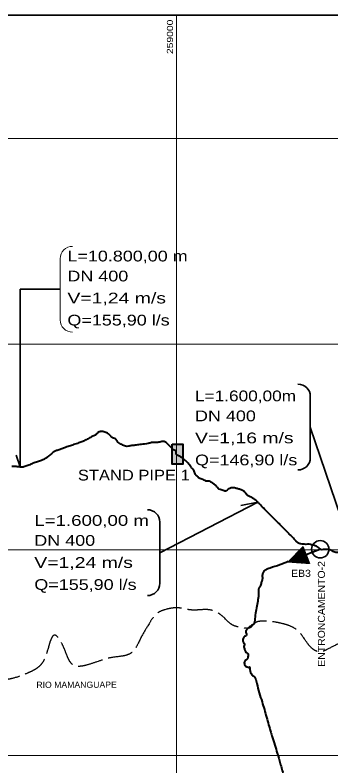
# Model space of a CAD drawing. Extents: x -4 to 42046, y -3 to 29697.
# Drawn here: x 35401 to 37843, y 13120 to 18930 of the extents above; entities that cross this region are included whole.
import ezdxf
from ezdxf.enums import TextEntityAlignment as Align

# ---------------------------------------------------------------- set-up
doc = ezdxf.new("R2010")
doc.units = 0
doc.header["$LTSCALE"] = 32
doc.linetypes.add('LONG_DASHED', pattern=[7.5, 6, -1.5])
for name, color, linetype, lineweight in [('4', 7, 'Continuous', 13), ('5', 7, 'LONG_DASHED', 25), ('6', 7, 'Continuous', 40), ('63', 7, 'Continuous', 25), ('8', 7, 'Continuous', 35)]:
    doc.layers.add(name, color=color, linetype=linetype, lineweight=lineweight)

msp = doc.modelspace()

# ---------------------------------------------------------------- hatches: boundary and pattern name
at = {"layer": '8'}
msp.add_hatch(color=256, dxfattribs=at).paths.add_polyline_path([(36615.72, 15610.25), (36697.35, 15610.25), (36697.35, 15455.76), (36615.72, 15455.76)])

# ---------------------------------------------------------------- linework, layer by layer
at = {"layer": '4'}
for p, q in [((37603.95, 14792.87), (37627.86, 14816.79)), ((37606.78, 14792.87), (37628.67, 14814.77)), ((37510.7, 14697.44), (37606.13, 14792.87)), ((37513.34, 14697.25), (37608.96, 14792.87)), ((37515.98, 14697.06), (37611.79, 14792.87)), ((37518.62, 14696.87), (37614.62, 14792.87)), ((37521.26, 14696.68), (37617.45, 14792.87)), ((37523.89, 14696.49), (37620.28, 14792.87)), ((37526.53, 14696.3), (37623.11, 14792.87)), ((37529.17, 14696.11), (37625.93, 14792.87)), ((37531.81, 14695.93), (37628.76, 14792.87)), ((37534.45, 14695.74), (37631.59, 14792.87)), ((37537.09, 14695.55), (37634.42, 14792.87)), ((37539.73, 14695.36), (37637.25, 14792.87)), ((37542.37, 14695.17), (37638.19, 14790.98)), ((37545.01, 14694.98), (37638.99, 14788.96)), ((37547.65, 14694.79), (37639.8, 14786.94)), ((37550.29, 14694.6), (37640.61, 14784.92)), ((37552.93, 14694.41), (37641.42, 14782.9)), ((37555.57, 14694.22), (37642.23, 14780.88)), ((37558.21, 14694.03), (37643.03, 14778.86)), ((37560.84, 14693.84), (37643.84, 14776.84)), ((37563.48, 14693.66), (37644.65, 14774.82)), ((37566.12, 14693.47), (37645.46, 14772.8)), ((37568.76, 14693.28), (37646.27, 14770.78)), ((37571.4, 14693.09), (37647.08, 14768.76)), ((37574.04, 14692.9), (37647.88, 14766.74)), ((37576.68, 14692.71), (37648.69, 14764.72)), ((37579.32, 14692.52), (37649.5, 14762.7)), ((37581.96, 14692.33), (37650.31, 14760.68)), ((37584.6, 14692.14), (37651.12, 14758.66)), ((37587.24, 14691.95), (37651.92, 14756.64)), ((37609.61, 14792.87), (37629.48, 14812.75)), ((37612.43, 14792.87), (37630.29, 14810.73)), ((37615.26, 14792.87), (37631.1, 14808.71)), ((37618.09, 14792.87), (37631.9, 14806.69)), ((37620.92, 14792.87), (37632.71, 14804.67)), ((37623.75, 14792.87), (37633.52, 14802.65)), ((37626.58, 14792.87), (37634.33, 14800.63)), ((37629.4, 14792.87), (37635.14, 14798.61)), ((37632.23, 14792.87), (37635.94, 14796.59)), ((37635.06, 14792.87), (37636.75, 14794.57)), ((37589.88, 14691.76), (37652.73, 14754.62)), ((37592.52, 14691.57), (37653.54, 14752.6)), ((37595.16, 14691.39), (37654.35, 14750.58)), ((37597.79, 14691.2), (37655.16, 14748.56)), ((37600.43, 14691.01), (37655.97, 14746.54)), ((37603.07, 14690.82), (37656.77, 14744.52)), ((37605.71, 14690.63), (37657.58, 14742.5)), ((37608.35, 14690.44), (37658.39, 14740.48)), ((37610.99, 14690.25), (37659.2, 14738.46)), ((37613.63, 14690.06), (37660.01, 14736.44)), ((37616.27, 14689.87), (37660.81, 14734.42)), ((37618.91, 14689.68), (37661.62, 14732.4)), ((37621.55, 14689.49), (37662.43, 14730.38)), ((37624.19, 14689.31), (37663.24, 14728.36)), ((37626.83, 14689.12), (37664.05, 14726.34)), ((37629.47, 14688.93), (37664.85, 14724.32)), ((37632.11, 14688.74), (37665.66, 14722.3)), ((37634.74, 14688.55), (37666.47, 14720.28)), ((37637.38, 14688.36), (37667.28, 14718.26)), ((37640.02, 14688.17), (37668.09, 14716.23)), ((37642.66, 14687.98), (37668.9, 14714.21)), ((37645.3, 14687.79), (37669.7, 14712.19)), ((37647.94, 14687.6), (37670.51, 14710.17)), ((37650.58, 14687.41), (37671.32, 14708.15)), ((37653.22, 14687.22), (37672.13, 14706.13)), ((37655.86, 14687.04), (37672.94, 14704.11)), ((37658.5, 14686.85), (37673.74, 14702.09)), ((37661.14, 14686.66), (37674.55, 14700.07)), ((37663.78, 14686.47), (37675.36, 14698.05)), ((37666.42, 14686.28), (37676.17, 14696.03)), ((37669.05, 14686.09), (37676.98, 14694.01)), ((37671.69, 14685.9), (37677.79, 14691.99)), ((37674.33, 14685.71), (37678.59, 14689.97)), ((37676.97, 14685.52), (37679.4, 14687.95)), ((37679.61, 14685.33), (37680.21, 14685.93))]:
    msp.add_line(p, q, dxfattribs=at)
msp.add_lwpolyline([(37680.47, 14685.27), (37509.34, 14697.54), (37627.58, 14817.5)], close=True, dxfattribs=at)
at = {"layer": '4', "lineweight": 35}
msp.add_ellipse((37760.11, 14797), major_axis=(67.17, 0), ratio=0.998913, dxfattribs=at)
at = {"layer": '5'}
for points in [[(36427.45, 14204.37), (36372.08, 14108.75), (36305.48, 13999.35), (36136.53, 13956.58), (35847.84, 13902.88), (35759.27, 14075.23), (35713.31, 14131.45), (35636.31, 13965.66), (35506.34, 13841.99), (35249.2, 13841.22), (35248.87, 13953.94), (35237.98, 13953.91), (35181.75, 14017.15), (35181.99, 13936.13), (35083.37, 13935.84), (34941.94, 14111.55), (34878.67, 14069.09), (34924.95, 13903.67), (34925.39, 13755.72), (34784.49, 13755.3), (34615.25, 13811.16), (34245.39, 13810.06), (34122.35, 13832.82), (34069.68, 13894.69), (33994.34, 13957.69), (33936.87, 14030.29), (33885.43, 14077.85), (33815, 14095.54), (33725.5, 14107.2), (33699.12, 14152.45), (33675.07, 14216.8), (33661.79, 14268.06), (33661.7, 14300.26), (33613.98, 14300.12), (33567.46, 14299.98), (33502.97, 14324.84), (33452.79, 14349.75), (33398.87, 14331.57), (33350.01, 14293.67), (33293.57, 14227.42), (33250.69, 14165.35), (33219.6, 14103.89), (33186.12, 14054.83), (33144.35, 14012.22), (33017.72, 14018.47), (32898.55, 14018.11), (32797.64, 14011.13), (32759.36, 14002.5), (32679.24, 13997.75), (32638.82, 14023.47), (32613.66, 14098.65), (32563.66, 14147.91), (32516.03, 14157.74), (32436.26, 14122.82), (32339.57, 14047.25), (32213.58, 14017.71), (32118.67, 13976.03), (32019.97, 13942.8), (31933.49, 13914.31), (31870.59, 13865.2), (31815.23, 13814.22), (31727.15, 13748.91), (31542.32, 13629.09), (31345.37, 13573.61), (31183.12, 13596.83), (31071.72, 13720.02), (31052.85, 13771.11), (30960.36, 13826.98), (30917.86, 13856.79), (30872.81, 13905.59), (30859.91, 13927.17), (30859.82, 13959.59), (30844.2, 13985.21), (30819.14, 14010.8), (30788.71, 14020.84), (30765.82, 13998.48), (30739.64, 13945.05), (30715.48, 13891.62), (30703.46, 13845.65), (30656.32, 13800.26), (30609.83, 13759.59), (30594.41, 13722.4), (30534.81, 13654.39), (30461.71, 13603.36), (30408.49, 13619.75), (30408.23, 13708.36), (30393.83, 13782.75), (30361.77, 13835.83), (30307.34, 13862.84), (30283.58, 13907.67), (30256.3, 13943.03)], [(38657.34, 14197.69), (38615.81, 14165.16), (38439.54, 14109.73), (38333.43, 14095.5), (38278.52, 14095.34), (38092.77, 14094.79), (37922.17, 14073.27), (37827.33, 14028.47), (37745.78, 14004.48), (37690.78, 14035.48), (37586.51, 14167.25), (37478.03, 14218.87), (37360.73, 14239.29), (37290.72, 14239.09), (37246.78, 14220.36), (37219.8, 14189.83), (37162.27, 14189.66), (37087.77, 14207.48), (36999.55, 14282.8), (36906.92, 14327.65), (36818.93, 14327.39), (36760.28, 14327.21), (36656.45, 14343.83), (36559.48, 14328.87), (36520.04, 14314.09), (36427.45, 14204.37)]]:
    msp.add_spline(points, degree=3, dxfattribs=at)
at = {"layer": '6'}
msp.add_line((37711.64, 14827.4), (37709.3, 14827.88), dxfattribs=at)
for points in [[(37709.3, 14827.88), (37675.49, 14834.82), (37649.22, 14834.74), (37610.85, 14837.96), (37597.67, 14840.66), (37586.49, 14846.55), (37577.62, 14855.11), (37558.3, 14875.82), (37537.47, 14897.44), (37518.92, 14916.48), (37503.91, 14932.32), (37490.68, 14945.47), (37454.57, 14981.71), (37428.17, 15007.7), (37392.89, 15043.28), (37351.33, 15084.86), (37323.4, 15113.4), (37289.86, 15147.79), (37274.92, 15162.72), (37262.26, 15176.45), (37242.73, 15188.43), (37218.79, 15202.7), (37198.7, 15212.9), (37188.55, 15225.19), (37173.64, 15242.38), (37148.17, 15256.23), (37123.57, 15263.97), (37097.95, 15270.73), (37071.51, 15270.65), (37049.44, 15260.36), (37033.24, 15249.85), (37022.75, 15245.94), (37010.38, 15250.37), (36995.03, 15255.94), (36977.3, 15262.02), (36970.56, 15266.4), (36960.87, 15280.85), (36943.85, 15296.92), (36921.42, 15311.91), (36895.45, 15324.15), (36877.32, 15324.09), (36862.22, 15332.21), (36845.64, 15338.88), (36828.6, 15344.01), (36820.22, 15350.25), (36809.38, 15361.82), (36800.2, 15369.5), (36793.97, 15379.39), (36788.29, 15394.26), (36780.16, 15408.52), (36768.81, 15422.83), (36759.72, 15434.61), (36749.99, 15449.33), (36738.11, 15462.88), (36725.52, 15476.7), (36710.64, 15489.75), (36693.22, 15503.6), (36673.28, 15515.93), (36655.41, 15524.39), (36648.63, 15528.88), (36646.01, 15534.47), (36645.95, 15552.79), (36626.26, 15566.61), (36613.27, 15577.62), (36592.72, 15598.36), (36579.15, 15612.69), (36560.1, 15627.83), (36528.24, 15627.74), (36498.3, 15622.4), (36457.08, 15622.28), (36430.02, 15614.28), (36375.01, 15607.78), (36337.68, 15602.94), (36304.09, 15598.1), (36276.94, 15593.5), (36255.36, 15593.43), (36239.99, 15598.9), (36212.17, 15614.92), (36196.51, 15625.77), (36182.48, 15646.27), (36155.26, 15658.54), (36139.79, 15673.03), (36122.74, 15689.61), (36095.16, 15702.51), (36062.06, 15707.32), (36040.08, 15698.45), (36027.88, 15684.37), (36015.29, 15676.38), (35991.9, 15665.76), (35968.42, 15651.91), (35949.96, 15642.78)], [(35949.96, 15642.78), (35924.86, 15630.39), (35892.83, 15619.16), (35854.12, 15605.83), (35820.11, 15594.68), (35782.73, 15580.71), (35755.81, 15570.3), (35727.11, 15561.87), (35704.96, 15552.01), (35674.66, 15528.78), (35651.71, 15510.22), (35627.85, 15494.05), (35605.75, 15483.71), (35575.2, 15472.87), (35538.97, 15461.54), (35507.35, 15447.76), (35476.95, 15437.52), (35463.03, 15431.98), (35441.56, 15431.91), (35410.29, 15436.5), (35375.55, 15436.4)], [(38174.6, 14663.29), (38127.22, 14673.83), (38076.54, 14685.21), (38047.55, 14694.39), (38012.34, 14706.01), (37988.11, 14715.31), (37967.81, 14723.05), (37954.24, 14728.92), (37942.51, 14737.58), (37932.73, 14746.93), (37918.26, 14759.96), (37893.41, 14771.8), (37880.94, 14771.76), (37852.21, 14784.5), (37814.89, 14794.46), (37801.49, 14794.42), (37781.92, 14794.36), (37763.21, 14794.3), (37758.96, 14799), (37746.47, 14810.8), (37731.41, 14819.91), (37711.64, 14827.4)], [(37760.11, 14797), (37700.68, 14772.56), (37652.67, 14754.74)], [(37513.14, 14701.44), (37447.67, 14676.15), (37371.97, 14651.28), (37339.23, 14638.17), (37320.84, 14621.8), (37312.56, 14600.55), (37312.65, 14571.68), (37306.6, 14545.96), (37297.93, 14516.75), (37286.48, 14495.69), (37282.98, 14457), (37278.69, 14406.46), (37270.86, 14356.33), (37260.27, 14301.11), (37253.33, 14245.13), (37250.44, 14224.3), (37247.06, 14217.9), (37238.22, 14210.98), (37220.26, 14200.13), (37207.62, 14190.59), (37195.1, 14179.43), (37185.23, 14162.53), (37189.4, 14139.3), (37190.79, 14134.45), (37190.84, 14134.62), (37186.28, 14129.72), (37173.63, 14120.7), (37162.23, 14098.62), (37167.69, 14074.38), (37174.62, 14062.76), (37174.87, 14061.72), (37171.33, 14051.02), (37173.62, 14026.79), (37182.97, 14005.81), (37196.14, 13992.51), (37203.1, 13986.6), (37204.12, 13983.9), (37202.63, 13972.69), (37200.37, 13956.41), (37198.06, 13950.97), (37194.26, 13946.08), (37184.24, 13939.18), (37172.94, 13918.46), (37182.75, 13893.01), (37203.26, 13883.62), (37216.64, 13881.82), (37215.75, 13883.76), (37219.38, 13855.75), (37225.76, 13835.22), (37239.69, 13818.53), (37252.09, 13809.09), (37258.05, 13800.04), (37270.33, 13757.77), (37310.51, 13615.91), (37345.03, 13497.72), (37378.08, 13381.5), (37389.02, 13344.71)], [(37388.59, 13346.26), (37427.93, 13218.17), (37450.7, 13140.3), (37477.17, 13050.5), (37493.3, 12996.04), (37498.18, 12976.54), (37499.55, 12969.64), (37485.73, 12897.94), (37470.56, 12818.38), (37444.11, 12683.26), (37412.66, 12506.42), (37403.58, 12461.37), (37401.48, 12454.75), (37389.27, 12437.29), (37366.5, 12413.37), (37344.72, 12391.46), (37326.68, 12372.25), (37314.05, 12359.13), (37280.52, 12325.61), (37185.56, 12226.97), (37108.82, 12147.79), (37045.3, 12082.37), (37021.69, 12053.47), (37000.96, 12025.99), (36995.12, 12017.71), (36960.08, 12023.74)]]:
    msp.add_spline(points, degree=3, dxfattribs=at)
at = {"layer": '63', "lineweight": 35}
msp.add_line((41110.1, 18929.66), (23907.83, 18929.66), dxfattribs=at)
at = {"layer": '63', "lineweight": 13}
for p, q in [((36650.26, 10019.66), (36650.26, 18929.66)), ((41110.1, 17975.02), (23907.83, 17975.02)), ((41110.1, 16383.95), (23907.83, 16383.95)), ((41110.1, 14792.87), (23907.83, 14792.87)), ((41110.1, 13201.8), (23907.83, 13201.8))]:
    msp.add_line(p, q, dxfattribs=at)
at = {"layer": '8', "lineweight": 13}
msp.add_line((35749.63, 16571.28), (35749.63, 17044.67), dxfattribs=at)
at = {"layer": '8'}
for p, q in [((37683.5, 15505.66), (37683.5, 15979.04)), ((36520.4, 14533.6), (36520.4, 15006.98))]:
    msp.add_line(p, q, dxfattribs=at)
for points in [[(35749.63, 16807.97), (35440.9, 16807.97), (35440.9, 15435.14), (35409.23, 15524.2)], [(37683.5, 15742.35), (38038.84, 14697.17), (38038.84, 14877.48)], [(36520.4, 14770.29), (37277.75, 15159.9), (37147.16, 15134.1)]]:
    msp.add_lwpolyline(points, dxfattribs=at)
at = {"layer": '8', "lineweight": 40}
msp.add_lwpolyline([(36615.72, 15610.25), (36697.35, 15610.25), (36697.35, 15455.76), (36615.72, 15455.76)], close=True, dxfattribs=at)
at = {"layer": '8', "lineweight": 13}
for centre, start_param, end_param in [((35845.2, 17044.67), 4.712389, 6.2831853), ((35845.2, 17044.67), 4.712389, 6.2831853), ((35845.2, 17044.67), 4.712389, 6.2831853), ((35845.2, 16571.28), 6.2831853, 7.8539816)]:
    msp.add_ellipse(centre, major_axis=(-95.57, 0), ratio=0.998913, start_param=start_param, end_param=end_param, dxfattribs=at)
at = {"layer": '8'}
for centre, start_param, end_param in [((37587.93, 15979.04), 6.2831853, 7.8539816), ((37587.93, 15979.04), 6.2831853, 7.8539816), ((37587.93, 15979.04), 6.2831853, 7.8539816), ((37587.93, 15505.66), 4.712389, 6.2831853), ((36424.83, 15006.98), 6.2831853, 7.8539816), ((36424.83, 15006.98), 6.2831853, 7.8539816), ((36424.83, 15006.98), 6.2831853, 7.8539816), ((36424.83, 14533.6), 4.712389, 6.2831853)]:
    msp.add_ellipse(centre, major_axis=(95.57, 0), ratio=0.998913, start_param=start_param, end_param=end_param, dxfattribs=at)

# ---------------------------------------------------------------- texts
at = {"layer": '4', "width": 1.1}
msp.add_text('ENTRONCAMENTO-2', height=55, rotation=90.006, dxfattribs=at).set_placement((37796.69, 14296.31), align=Align.CENTER)
at = {"layer": '5', "width": 1.1}
msp.add_text('EB3', height=55, rotation=0.006, dxfattribs=at).set_placement((37611.63, 14583.04), align=Align.CENTER)
at = {"layer": '5', "width": 1.05}
msp.add_text('RIO MAMANGUAPE', height=47.73, rotation=0.111, dxfattribs=at).set_placement((35565.9, 13723.95))
at = {"layer": '8', "width": 1.25}
msp.add_text('259000', height=47.78, rotation=90, dxfattribs=at).set_placement((36622.5, 18627.41))
at = {"layer": '8'}
for s, width, p in [('L=10.800,00 m', 1.25, (35805.93, 17023.44)), ('DN 400', 1.25, (35805.93, 16868.95)), ('V=1,24 m/s', 1.35, (35805.93, 16698.36)), ('Q=155,90 l/s', 1.25, (35805.93, 16527.77)), ('L=1.600,00m', 1.2, (36792.18, 15941.52)), ('DN 400', 1.25, (36792.18, 15787.03)), ('V=1,16 m/s', 1.35, (36792.18, 15616.44)), ('Q=146,90 l/s', 1.25, (36792.18, 15445.85)), ('STAND PIPE 1', 1.15, (35886.62, 15328.63)), ('L=1.600,00 m', 1.3, (35550.11, 14977.88)), ('DN 400', 1.25, (35550.11, 14823.38)), ('V=1,24 m/s', 1.35, (35550.11, 14652.79)), ('Q=155,90 l/s', 1.25, (35550.11, 14482.2))]:
    msp.add_text(s, height=82.98, dxfattribs=dict(at, width=width)).set_placement(p)

doc.saveas('drawing.dxf')
